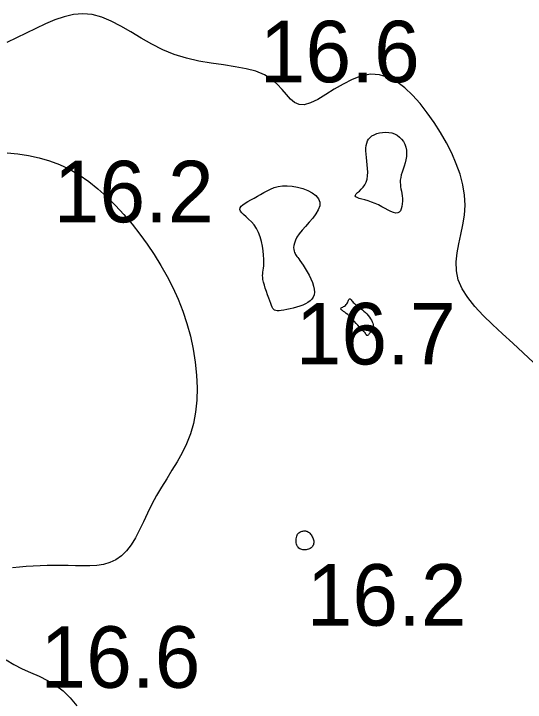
# Model space of a CAD drawing. Extents: x 3040093 to 3056816, y 408076 to 509144.
# Drawn here: x 3045524.8 to 3045566.4, y 433877.9 to 433933.8 of the extents above; entities that cross this region are included whole.
import ezdxf

# ---------------------------------------------------------------- set-up
doc = ezdxf.new("R2010")
doc.units = 0
doc.layers.add('V-CHAN-CONT-EL17', color=7, linetype='Continuous')
doc.layers.add('V-TOPO-SOUN-0610', color=7, linetype='Continuous')

msp = doc.modelspace()

# ---------------------------------------------------------------- linework, layer by layer
at = {"layer": 'V-CHAN-CONT-EL17'}
for points in [[(3045567.089, 433905.512), (3045566.257, 433906.304), (3045565.412, 433907.079), (3045564.575, 433907.84), (3045563.767, 433908.588), (3045563.013, 433909.327), (3045562.334, 433910.057), (3045561.755, 433910.783), (3045561.296, 433911.506), (3045560.982, 433912.228), (3045560.826, 433912.953), (3045560.803, 433913.681), (3045560.879, 433914.417), (3045561.019, 433915.161), (3045561.189, 433915.917), (3045561.355, 433916.688), (3045561.483, 433917.475), (3045561.539, 433918.281), (3045561.495, 433919.107), (3045561.353, 433919.95), (3045561.125, 433920.802), (3045560.818, 433921.659), (3045560.444, 433922.515), (3045560.01, 433923.364), (3045559.528, 433924.2), (3045559.007, 433925.018), (3045558.454, 433925.81), (3045557.874, 433926.557), (3045557.266, 433927.238), (3045556.631, 433927.833), (3045555.972, 433928.321), (3045555.289, 433928.681), (3045554.583, 433928.892), (3045553.856, 433928.933), (3045553.11, 433928.795), (3045552.357, 433928.514), (3045551.611, 433928.136), (3045550.886, 433927.709), (3045550.194, 433927.28), (3045549.549, 433926.895), (3045548.965, 433926.602), (3045548.456, 433926.448), (3045548.028, 433926.466), (3045547.66, 433926.635), (3045547.326, 433926.921), (3045546.999, 433927.29), (3045546.65, 433927.706), (3045546.254, 433928.136), (3045545.783, 433928.545), (3045545.21, 433928.899), (3045544.515, 433929.172), (3045543.713, 433929.378), (3045542.826, 433929.542), (3045541.875, 433929.686), (3045540.883, 433929.834), (3045539.873, 433930.01), (3045538.865, 433930.236), (3045537.882, 433930.537), (3045536.941, 433930.927), (3045536.042, 433931.383), (3045535.179, 433931.876), (3045534.347, 433932.373), (3045533.539, 433932.843), (3045532.751, 433933.256), (3045531.977, 433933.581), (3045531.211, 433933.786), (3045530.448, 433933.849), (3045529.686, 433933.783), (3045528.924, 433933.61), (3045528.16, 433933.351), (3045527.392, 433933.027), (3045526.619, 433932.662), (3045525.838, 433932.275), (3045525.049, 433931.889), (3045524.25, 433931.525)], [(3045524.283, 433922.546), (3045525.164, 433922.463), (3045526.033, 433922.334), (3045526.887, 433922.15), (3045527.726, 433921.907), (3045528.549, 433921.597), (3045529.355, 433921.214), (3045530.145, 433920.754), (3045530.915, 433920.222), (3045531.666, 433919.626), (3045532.395, 433918.974), (3045533.102, 433918.272), (3045533.785, 433917.528), (3045534.444, 433916.75), (3045535.077, 433915.945), (3045535.681, 433915.119), (3045536.256, 433914.272), (3045536.798, 433913.403), (3045537.303, 433912.51), (3045537.77, 433911.591), (3045538.194, 433910.646), (3045538.574, 433909.673), (3045538.906, 433908.67), (3045539.187, 433907.638), (3045539.414, 433906.587), (3045539.584, 433905.529), (3045539.692, 433904.476), (3045539.735, 433903.44), (3045539.71, 433902.433), (3045539.613, 433901.468), (3045539.441, 433900.556), (3045539.192, 433899.705), (3045538.879, 433898.91), (3045538.515, 433898.158), (3045538.115, 433897.44), (3045537.692, 433896.745), (3045537.262, 433896.062), (3045536.838, 433895.38), (3045536.434, 433894.689), (3045536.061, 433893.982), (3045535.713, 433893.271), (3045535.379, 433892.571), (3045535.051, 433891.898), (3045534.717, 433891.267), (3045534.368, 433890.693), (3045533.994, 433890.193), (3045533.584, 433889.782), (3045533.133, 433889.469), (3045532.643, 433889.247), (3045532.121, 433889.101), (3045531.573, 433889.015), (3045531.006, 433888.978), (3045530.427, 433888.973), (3045529.841, 433888.987), (3045529.255, 433889.005), (3045528.674, 433889.016), (3045528.099, 433889.017), (3045527.529, 433889.008), (3045526.963, 433888.988), (3045526.4, 433888.959), (3045525.839, 433888.919), (3045525.279, 433888.868), (3045524.72, 433888.807)], [(3045524.199, 433881.338), (3045524.837, 433880.955), (3045525.504, 433880.622), (3045526.189, 433880.315), (3045526.877, 433880.006), (3045527.557, 433879.671), (3045528.215, 433879.283), (3045528.839, 433878.817), (3045529.418, 433878.254), (3045529.956, 433877.601)]]:
    msp.add_lwpolyline(points, dxfattribs=at)
for points in [[(3045553.922, 433918.549), (3045553.643, 433918.641), (3045553.377, 433918.719), (3045553.136, 433918.787), (3045552.928, 433918.848), (3045552.762, 433918.908), (3045552.648, 433918.971), (3045552.596, 433919.039), (3045552.61, 433919.117), (3045552.681, 433919.207), (3045552.795, 433919.313), (3045552.936, 433919.437), (3045553.091, 433919.581), (3045553.246, 433919.748), (3045553.386, 433919.94), (3045553.498, 433920.16), (3045553.57, 433920.41), (3045553.607, 433920.683), (3045553.615, 433920.974), (3045553.601, 433921.275), (3045553.574, 433921.58), (3045553.539, 433921.882), (3045553.504, 433922.174), (3045553.476, 433922.45), (3045553.461, 433922.704), (3045553.464, 433922.936), (3045553.485, 433923.147), (3045553.528, 433923.338), (3045553.594, 433923.509), (3045553.687, 433923.662), (3045553.808, 433923.798), (3045553.96, 433923.917), (3045554.143, 433924.02), (3045554.353, 433924.105), (3045554.583, 433924.17), (3045554.826, 433924.211), (3045555.076, 433924.226), (3045555.327, 433924.212), (3045555.571, 433924.168), (3045555.802, 433924.089), (3045556.014, 433923.976), (3045556.204, 433923.83), (3045556.371, 433923.655), (3045556.513, 433923.457), (3045556.626, 433923.238), (3045556.71, 433923.003), (3045556.762, 433922.756), (3045556.78, 433922.501), (3045556.764, 433922.242), (3045556.72, 433921.981), (3045556.655, 433921.722), (3045556.578, 433921.466), (3045556.495, 433921.217), (3045556.415, 433920.976), (3045556.345, 433920.748), (3045556.294, 433920.533), (3045556.265, 433920.334), (3045556.258, 433920.148), (3045556.268, 433919.97), (3045556.29, 433919.796), (3045556.32, 433919.622), (3045556.353, 433919.443), (3045556.385, 433919.255), (3045556.412, 433919.055), (3045556.429, 433918.839), (3045556.434, 433918.615), (3045556.423, 433918.394), (3045556.394, 433918.185), (3045556.345, 433917.997), (3045556.273, 433917.841), (3045556.175, 433917.726), (3045556.049, 433917.662), (3045555.892, 433917.655), (3045555.708, 433917.698), (3045555.499, 433917.782), (3045555.27, 433917.895), (3045555.022, 433918.028), (3045554.76, 433918.17), (3045554.487, 433918.311), (3045554.206, 433918.44)], [(3045544.365, 433916.697), (3045544.149, 433916.947), (3045543.928, 433917.165), (3045543.714, 433917.356), (3045543.521, 433917.524), (3045543.363, 433917.675), (3045543.252, 433917.813), (3045543.204, 433917.945), (3045543.226, 433918.073), (3045543.314, 433918.2), (3045543.456, 433918.328), (3045543.643, 433918.457), (3045543.865, 433918.589), (3045544.112, 433918.725), (3045544.373, 433918.865), (3045544.639, 433919.012), (3045544.902, 433919.166), (3045545.165, 433919.319), (3045545.433, 433919.467), (3045545.713, 433919.602), (3045546.009, 433919.717), (3045546.328, 433919.805), (3045546.675, 433919.859), (3045547.055, 433919.873), (3045547.47, 433919.842), (3045547.904, 433919.766), (3045548.334, 433919.648), (3045548.742, 433919.492), (3045549.105, 433919.3), (3045549.404, 433919.076), (3045549.617, 433918.822), (3045549.724, 433918.54), (3045549.711, 433918.236), (3045549.594, 433917.913), (3045549.397, 433917.58), (3045549.144, 433917.241), (3045548.859, 433916.903), (3045548.565, 433916.572), (3045548.285, 433916.256), (3045548.044, 433915.959), (3045547.859, 433915.687), (3045547.729, 433915.441), (3045547.646, 433915.219), (3045547.601, 433915.021), (3045547.588, 433914.847), (3045547.599, 433914.694), (3045547.626, 433914.563), (3045547.662, 433914.453), (3045547.7, 433914.362), (3045547.742, 433914.283), (3045547.79, 433914.208), (3045547.847, 433914.129), (3045547.916, 433914.038), (3045548, 433913.928), (3045548.101, 433913.791), (3045548.222, 433913.618), (3045548.363, 433913.405), (3045548.519, 433913.157), (3045548.681, 433912.885), (3045548.838, 433912.596), (3045548.984, 433912.3), (3045549.109, 433912.006), (3045549.205, 433911.723), (3045549.262, 433911.46), (3045549.275, 433911.224), (3045549.244, 433911.014), (3045549.172, 433910.829), (3045549.064, 433910.665), (3045548.921, 433910.519), (3045548.748, 433910.391), (3045548.548, 433910.276), (3045548.323, 433910.173), (3045548.079, 433910.08), (3045547.82, 433909.996), (3045547.556, 433909.922), (3045547.293, 433909.859), (3045547.038, 433909.806), (3045546.799, 433909.765), (3045546.584, 433909.735), (3045546.399, 433909.717), (3045546.25, 433909.713), (3045546.133, 433909.725), (3045546.04, 433909.755), (3045545.966, 433909.807), (3045545.904, 433909.885), (3045545.847, 433909.991), (3045545.789, 433910.129), (3045545.723, 433910.301), (3045545.645, 433910.509), (3045545.557, 433910.746), (3045545.465, 433911.002), (3045545.372, 433911.268), (3045545.284, 433911.535), (3045545.205, 433911.793), (3045545.141, 433912.033), (3045545.095, 433912.246), (3045545.071, 433912.426), (3045545.066, 433912.581), (3045545.075, 433912.721), (3045545.093, 433912.859), (3045545.117, 433913.005), (3045545.141, 433913.172), (3045545.16, 433913.369), (3045545.17, 433913.608), (3045545.168, 433913.897), (3045545.148, 433914.227), (3045545.111, 433914.587), (3045545.052, 433914.965), (3045544.971, 433915.347), (3045544.863, 433915.724), (3045544.727, 433916.082), (3045544.561, 433916.409)], [(3045551.424, 433909.907), (3045551.462, 433909.938), (3045551.516, 433909.971), (3045551.582, 433910.007), (3045551.654, 433910.048), (3045551.729, 433910.094), (3045551.802, 433910.147), (3045551.867, 433910.208), (3045551.922, 433910.277), (3045551.968, 433910.352), (3045552.005, 433910.429), (3045552.036, 433910.502), (3045552.062, 433910.569), (3045552.086, 433910.626), (3045552.11, 433910.667), (3045552.134, 433910.69), (3045552.162, 433910.692), (3045552.193, 433910.673), (3045552.228, 433910.639), (3045552.269, 433910.59), (3045552.316, 433910.532), (3045552.37, 433910.466), (3045552.431, 433910.395), (3045552.501, 433910.324), (3045552.58, 433910.253), (3045552.667, 433910.183), (3045552.761, 433910.111), (3045552.861, 433910.037), (3045552.967, 433909.958), (3045553.077, 433909.873), (3045553.19, 433909.781), (3045553.305, 433909.68), (3045553.421, 433909.569), (3045553.535, 433909.449), (3045553.645, 433909.324), (3045553.748, 433909.197), (3045553.841, 433909.068), (3045553.922, 433908.941), (3045553.986, 433908.819), (3045554.033, 433908.704), (3045554.059, 433908.598), (3045554.066, 433908.501), (3045554.058, 433908.411), (3045554.038, 433908.327), (3045554.007, 433908.249), (3045553.969, 433908.176), (3045553.926, 433908.107), (3045553.881, 433908.04), (3045553.837, 433907.975), (3045553.794, 433907.914), (3045553.753, 433907.858), (3045553.713, 433907.807), (3045553.675, 433907.765), (3045553.64, 433907.732), (3045553.607, 433907.711), (3045553.577, 433907.702), (3045553.551, 433907.706), (3045553.526, 433907.721), (3045553.504, 433907.746), (3045553.483, 433907.778), (3045553.463, 433907.813), (3045553.443, 433907.85), (3045553.423, 433907.886), (3045553.401, 433907.919), (3045553.378, 433907.947), (3045553.352, 433907.972), (3045553.321, 433908), (3045553.282, 433908.032), (3045553.234, 433908.073), (3045553.175, 433908.128), (3045553.104, 433908.198), (3045553.017, 433908.289), (3045552.915, 433908.402), (3045552.8, 433908.534), (3045552.674, 433908.678), (3045552.541, 433908.829), (3045552.403, 433908.983), (3045552.264, 433909.132), (3045552.127, 433909.272), (3045551.995, 433909.397), (3045551.871, 433909.502), (3045551.757, 433909.59), (3045551.655, 433909.662), (3045551.567, 433909.721), (3045551.497, 433909.769), (3045551.445, 433909.81), (3045551.414, 433909.844), (3045551.407, 433909.876)], [(3045548.336, 433890.281), (3045548.25, 433890.301), (3045548.167, 433890.332), (3045548.09, 433890.374), (3045548.019, 433890.426), (3045547.956, 433890.49), (3045547.901, 433890.564), (3045547.857, 433890.65), (3045547.823, 433890.746), (3045547.8, 433890.851), (3045547.788, 433890.961), (3045547.786, 433891.073), (3045547.793, 433891.185), (3045547.81, 433891.292), (3045547.836, 433891.392), (3045547.871, 433891.481), (3045547.915, 433891.558), (3045547.965, 433891.623), (3045548.021, 433891.677), (3045548.082, 433891.72), (3045548.146, 433891.754), (3045548.213, 433891.78), (3045548.28, 433891.799), (3045548.347, 433891.812), (3045548.413, 433891.82), (3045548.478, 433891.821), (3045548.541, 433891.817), (3045548.603, 433891.806), (3045548.664, 433891.787), (3045548.724, 433891.76), (3045548.783, 433891.725), (3045548.841, 433891.68), (3045548.899, 433891.625), (3045548.955, 433891.562), (3045549.009, 433891.491), (3045549.059, 433891.415), (3045549.104, 433891.335), (3045549.144, 433891.252), (3045549.177, 433891.168), (3045549.202, 433891.084), (3045549.218, 433891.002), (3045549.226, 433890.922), (3045549.224, 433890.844), (3045549.213, 433890.769), (3045549.192, 433890.697), (3045549.162, 433890.629), (3045549.122, 433890.566), (3045549.071, 433890.507), (3045549.011, 433890.453), (3045548.942, 433890.404), (3045548.866, 433890.362), (3045548.783, 433890.327), (3045548.697, 433890.3), (3045548.607, 433890.281), (3045548.516, 433890.271), (3045548.426, 433890.271)]]:
    msp.add_lwpolyline(points, close=True, dxfattribs=at)

# ---------------------------------------------------------------- texts
at = {"layer": 'V-TOPO-SOUN-0610'}
for s, p in [('16.6 ', (3045544.833, 433928.28)), ('16.2 ', (3045528.073, 433916.9)), ('16.7 ', (3045547.753, 433905.35)), ('16.2 ', (3045548.643, 433884.12)), ('16.6 ', (3045526.993, 433879.07))]:
    msp.add_text(s, height=5, dxfattribs=at).set_placement(p)

doc.saveas('drawing.dxf')
